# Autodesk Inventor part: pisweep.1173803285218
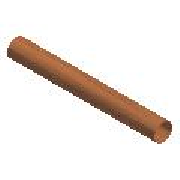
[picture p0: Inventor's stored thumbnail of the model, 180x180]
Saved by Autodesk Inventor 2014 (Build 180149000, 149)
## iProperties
NAME: PIPING: ASTM B 88 Tube
DATA: <meta><inlinegroups number="1" deflen="254"></inlinegroups><connections number="2"></connections><angles><a>3.14159265358979</a></angles></meta>
Company: Autodesk, Inc.
Created: 2007-02
Material: Copper
Description: Pipe
Document SubType Name: Modeling
Standard: ASTM B 88
Designer: Autodesk, Inc.
Standard Revision: 2003
Standards Organization: ANSI
Language: en-US
Size Designation: 3/4 - Type L - 100
Categories: <MemberInstance><Categories><Category DisplayName="Tube &amp; Pipe" InternalName="4347fa0f-2144-441d-94cd-e3e15c92b736" Mnemonic="TUBEANDPIPE"><CategoryParamete
Stock Number: ASTM B 88 Tube 3/4 - Type L
Density: 8.94 g/cm^3
Appearance: Copper
L: 17.348 in
PL: 17.348 in
Author: Autodesk, Inc.
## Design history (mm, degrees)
sketch "3D Sketch1" dims "d4" = 50.7999, "d5" = 50.7999
workpoint "Work Point3"
workpoint "Work Point4"
workpoint "Work Point5"
workpoint "Work Point6"
workplane "Work Plane1"
sketch "Sketch3"
  geometry: C1 r 11.113 at (0, 0); C2 r 9.97 at (0, 0); 1 further point
  constraints: 2 centre point
workpoint "Work Point7"
sweep "Sweep1" dims "d6" = 0
body "Solid1"
other parameters: "OD" = 22.225 [user parameter], "t" = 1.143 [user parameter], "L" = 440.6392 (= PL) [user parameter], "ID" = 19.939 [user parameter], "PL" = 440.6392 [user parameter; used in 1 equation term], "Size_Designation" = 12.345 [user parameter]
